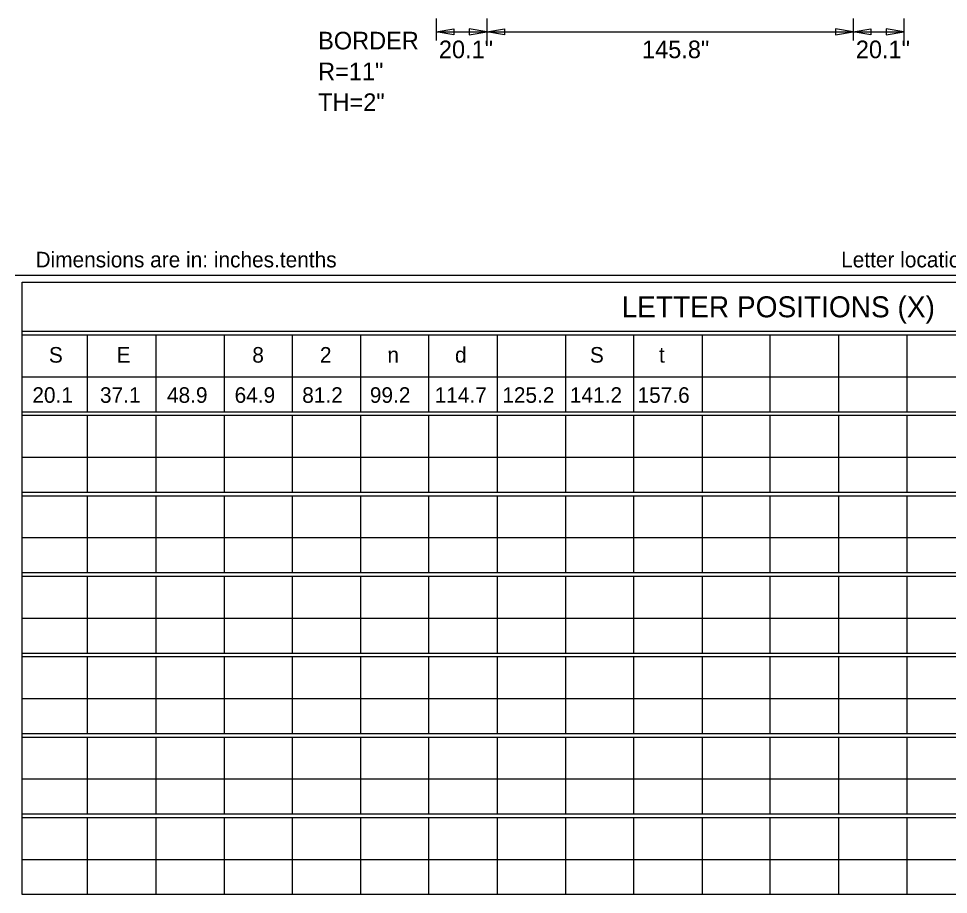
# Model space of a CAD drawing. Extents: x 2150010 to 2150174, y 145114 to 145224.
# Drawn here: x 2150076.43 to 2150107.26, y 145167.18 to 145196.22 of the extents above; entities that cross this region are included whole.
import ezdxf

# ---------------------------------------------------------------- set-up
doc = ezdxf.new("R2010")
doc.units = 0
doc.layers.add('GSDIMS', color=7, linetype='Continuous')
doc.layers.add('Level 1', color=7, linetype='Continuous')

msp = doc.modelspace()

# ---------------------------------------------------------------- linework, layer by layer
at = {"layer": 'GSDIMS'}
for p, q in [((2150090.279, 145196.216), (2150090.279, 145195.486)), ((2150090.279, 145196.216), (2150090.279, 145195.486)), ((2150091.955, 145196.216), (2150091.955, 145195.486)), ((2150091.955, 145196.216), (2150091.955, 145195.486)), ((2150104.102, 145196.216), (2150104.102, 145195.486)), ((2150104.102, 145196.216), (2150104.102, 145195.486)), ((2150105.779, 145196.216), (2150105.779, 145195.486)), ((2150105.779, 145196.216), (2150105.779, 145195.486)), ((2150090.279, 145195.778), (2150091.955, 145195.778)), ((2150091.955, 145195.778), (2150104.102, 145195.778)), ((2150104.102, 145195.778), (2150105.779, 145195.778))]:
    msp.add_line(p, q, dxfattribs=at)
for points in [[(2150090.279, 145195.778), (2150090.862, 145195.875), (2150090.862, 145195.681)], [(2150091.955, 145195.778), (2150091.372, 145195.875), (2150091.372, 145195.681)], [(2150091.955, 145195.778), (2150092.539, 145195.875), (2150092.539, 145195.681)], [(2150104.102, 145195.778), (2150103.519, 145195.875), (2150103.519, 145195.681)], [(2150104.102, 145195.778), (2150104.685, 145195.875), (2150104.685, 145195.681)], [(2150105.779, 145195.778), (2150105.195, 145195.875), (2150105.195, 145195.681)]]:
    msp.add_lwpolyline(points, close=True, dxfattribs=at)
at = {"layer": 'Level 1'}
for p, q in [((2150076.316, 145187.705), (2150121.342, 145187.705)), ((2150076.548, 145185.849), (2150134.843, 145185.849)), ((2150076.548, 145185.733), (2150134.843, 145185.733)), ((2150078.704, 145185.733), (2150078.704, 145183.183)), ((2150080.977, 145185.733), (2150080.977, 145183.183)), ((2150083.25, 145185.733), (2150083.25, 145183.183)), ((2150085.499, 145185.733), (2150085.499, 145183.183)), ((2150087.772, 145185.733), (2150087.772, 145183.183)), ((2150090.021, 145185.733), (2150090.021, 145183.183)), ((2150092.294, 145185.733), (2150092.294, 145183.183)), ((2150094.566, 145185.733), (2150094.566, 145183.183)), ((2150096.816, 145185.733), (2150096.816, 145183.183)), ((2150099.088, 145185.733), (2150099.088, 145183.183)), ((2150101.337, 145185.733), (2150101.337, 145183.183)), ((2150103.61, 145185.733), (2150103.61, 145183.183)), ((2150105.883, 145185.733), (2150105.883, 145183.183)), ((2150076.548, 145184.342), (2150126.185, 145184.342)), ((2150076.548, 145183.183), (2150134.843, 145183.183)), ((2150076.548, 145183.067), (2150134.843, 145183.067)), ((2150078.704, 145183.067), (2150078.704, 145180.516)), ((2150080.977, 145183.067), (2150080.977, 145180.516)), ((2150083.25, 145183.067), (2150083.25, 145180.516)), ((2150085.499, 145183.067), (2150085.499, 145180.516)), ((2150087.772, 145183.067), (2150087.772, 145180.516)), ((2150090.021, 145183.067), (2150090.021, 145180.516)), ((2150092.294, 145183.067), (2150092.294, 145180.516)), ((2150094.566, 145183.067), (2150094.566, 145180.516)), ((2150096.816, 145183.067), (2150096.816, 145180.516)), ((2150099.088, 145183.067), (2150099.088, 145180.516)), ((2150101.337, 145183.067), (2150101.337, 145180.516)), ((2150103.61, 145183.067), (2150103.61, 145180.516)), ((2150105.883, 145183.067), (2150105.883, 145180.516)), ((2150076.548, 145181.675), (2150126.185, 145181.675)), ((2150076.548, 145180.516), (2150134.843, 145180.516)), ((2150076.548, 145180.4), (2150134.843, 145180.4)), ((2150078.704, 145180.4), (2150078.704, 145177.849)), ((2150080.977, 145180.4), (2150080.977, 145177.849)), ((2150083.25, 145180.4), (2150083.25, 145177.849)), ((2150085.499, 145180.4), (2150085.499, 145177.849)), ((2150087.772, 145180.4), (2150087.772, 145177.849)), ((2150090.021, 145180.4), (2150090.021, 145177.849)), ((2150092.294, 145180.4), (2150092.294, 145177.849)), ((2150094.566, 145180.4), (2150094.566, 145177.849)), ((2150096.816, 145180.4), (2150096.816, 145177.849)), ((2150099.088, 145180.4), (2150099.088, 145177.849)), ((2150101.337, 145180.4), (2150101.337, 145177.849)), ((2150103.61, 145180.4), (2150103.61, 145177.849)), ((2150105.883, 145180.4), (2150105.883, 145177.849)), ((2150076.548, 145179.008), (2150126.185, 145179.008)), ((2150076.548, 145177.849), (2150134.843, 145177.849)), ((2150076.548, 145177.733), (2150134.843, 145177.733)), ((2150078.704, 145177.733), (2150078.704, 145175.182)), ((2150080.977, 145177.733), (2150080.977, 145175.182)), ((2150083.25, 145177.733), (2150083.25, 145175.182)), ((2150085.499, 145177.733), (2150085.499, 145175.182)), ((2150087.772, 145177.733), (2150087.772, 145175.182)), ((2150090.021, 145177.733), (2150090.021, 145175.182)), ((2150092.294, 145177.733), (2150092.294, 145175.182)), ((2150094.566, 145177.733), (2150094.566, 145175.182)), ((2150096.816, 145177.733), (2150096.816, 145175.182)), ((2150099.088, 145177.733), (2150099.088, 145175.182)), ((2150101.337, 145177.733), (2150101.337, 145175.182)), ((2150103.61, 145177.733), (2150103.61, 145175.182)), ((2150105.883, 145177.733), (2150105.883, 145175.182)), ((2150076.548, 145176.342), (2150126.185, 145176.342)), ((2150076.548, 145175.182), (2150134.843, 145175.182)), ((2150076.548, 145175.066), (2150134.843, 145175.066)), ((2150078.704, 145175.066), (2150078.704, 145172.515)), ((2150080.977, 145175.066), (2150080.977, 145172.515)), ((2150083.25, 145175.066), (2150083.25, 145172.515)), ((2150085.499, 145175.066), (2150085.499, 145172.515)), ((2150087.772, 145175.066), (2150087.772, 145172.515)), ((2150090.021, 145175.066), (2150090.021, 145172.515)), ((2150092.294, 145175.066), (2150092.294, 145172.515)), ((2150094.566, 145175.066), (2150094.566, 145172.515)), ((2150096.816, 145175.066), (2150096.816, 145172.515)), ((2150099.088, 145175.066), (2150099.088, 145172.515)), ((2150101.337, 145175.066), (2150101.337, 145172.515)), ((2150103.61, 145175.066), (2150103.61, 145172.515)), ((2150105.883, 145175.066), (2150105.883, 145172.515)), ((2150076.548, 145173.675), (2150126.185, 145173.675)), ((2150076.548, 145172.515), (2150134.843, 145172.515)), ((2150076.548, 145172.399), (2150134.843, 145172.399)), ((2150078.704, 145172.399), (2150078.704, 145169.849)), ((2150080.977, 145172.399), (2150080.977, 145169.849)), ((2150083.25, 145172.399), (2150083.25, 145169.849)), ((2150085.499, 145172.399), (2150085.499, 145169.849)), ((2150087.772, 145172.399), (2150087.772, 145169.849)), ((2150090.021, 145172.399), (2150090.021, 145169.849)), ((2150092.294, 145172.399), (2150092.294, 145169.849)), ((2150094.566, 145172.399), (2150094.566, 145169.849)), ((2150096.816, 145172.399), (2150096.816, 145169.849)), ((2150099.088, 145172.399), (2150099.088, 145169.849)), ((2150101.337, 145172.399), (2150101.337, 145169.849)), ((2150103.61, 145172.399), (2150103.61, 145169.849)), ((2150105.883, 145172.399), (2150105.883, 145169.849)), ((2150076.548, 145171.008), (2150126.185, 145171.008)), ((2150076.548, 145169.849), (2150134.843, 145169.849)), ((2150076.548, 145169.733), (2150134.843, 145169.733)), ((2150078.704, 145169.733), (2150078.704, 145167.182)), ((2150080.977, 145169.733), (2150080.977, 145167.182)), ((2150083.25, 145169.733), (2150083.25, 145167.182)), ((2150085.499, 145169.733), (2150085.499, 145167.182)), ((2150087.772, 145169.733), (2150087.772, 145167.182)), ((2150090.021, 145169.733), (2150090.021, 145167.182)), ((2150092.294, 145169.733), (2150092.294, 145167.182)), ((2150094.566, 145169.733), (2150094.566, 145167.182)), ((2150096.816, 145169.733), (2150096.816, 145167.182)), ((2150099.088, 145169.733), (2150099.088, 145167.182)), ((2150101.337, 145169.733), (2150101.337, 145167.182)), ((2150103.61, 145169.733), (2150103.61, 145167.182)), ((2150105.883, 145169.733), (2150105.883, 145167.182)), ((2150076.548, 145168.341), (2150126.185, 145168.341))]:
    msp.add_line(p, q, dxfattribs=at)
msp.add_lwpolyline([(2150076.548, 145187.473), (2150134.843, 145187.473), (2150134.843, 145167.182), (2150076.548, 145167.182)], close=True, dxfattribs=at)

# ---------------------------------------------------------------- texts
at = {"layer": 'GSDIMS'}
for s, p in [('BORDER', (2150086.362, 145195.195)), ('20.1"', (2150090.365, 145194.903)), ('145.8"', (2150097.1, 145194.903)), ('20.1"', (2150104.188, 145194.903)), ('R=11"', (2150086.362, 145194.174)), ('TH=2"', (2150086.362, 145193.153))]:
    msp.add_text(s, height=0.5833, dxfattribs=at).set_placement(p)
at = {"layer": 'Level 1'}
for s, height, p in [('Dimensions are in: inches.tenths', 0.51652, (2150076.993, 145187.968)), ('Letter locations are panel edge to lower left corner', 0.51652, (2150103.701, 145187.968)), ('LETTER POSITIONS (X)', 0.69555, (2150096.422, 145186.313)), ('S', 0.517, (2150077.437, 145184.81)), ('E', 0.517, (2150079.679, 145184.81)), ('8', 0.517, (2150084.179, 145184.81)), ('2', 0.517, (2150086.421, 145184.81)), ('d', 0.517, (2150090.9, 145184.81)), ('S', 0.517, (2150095.372, 145184.81)), ('t', 0.517, (2150097.661, 145184.81)), ('n', 0.517, (2150088.658, 145184.81)), ('20.1', 0.5165, (2150076.888, 145183.478)), ('37.1', 0.5165, (2150079.13, 145183.478)), ('48.9', 0.5165, (2150081.351, 145183.478)), ('64.9', 0.5165, (2150083.593, 145183.478)), ('81.2', 0.5165, (2150085.835, 145183.478)), ('99.2', 0.5165, (2150088.077, 145183.478)), ('114.7', 0.5165, (2150090.225, 145183.478)), ('125.2', 0.5165, (2150092.467, 145183.478)), ('141.2', 0.5165, (2150094.709, 145183.478)), ('157.6', 0.5165, (2150096.951, 145183.478))]:
    msp.add_text(s, height=height, dxfattribs=at).set_placement(p)

doc.saveas('drawing.dxf')
